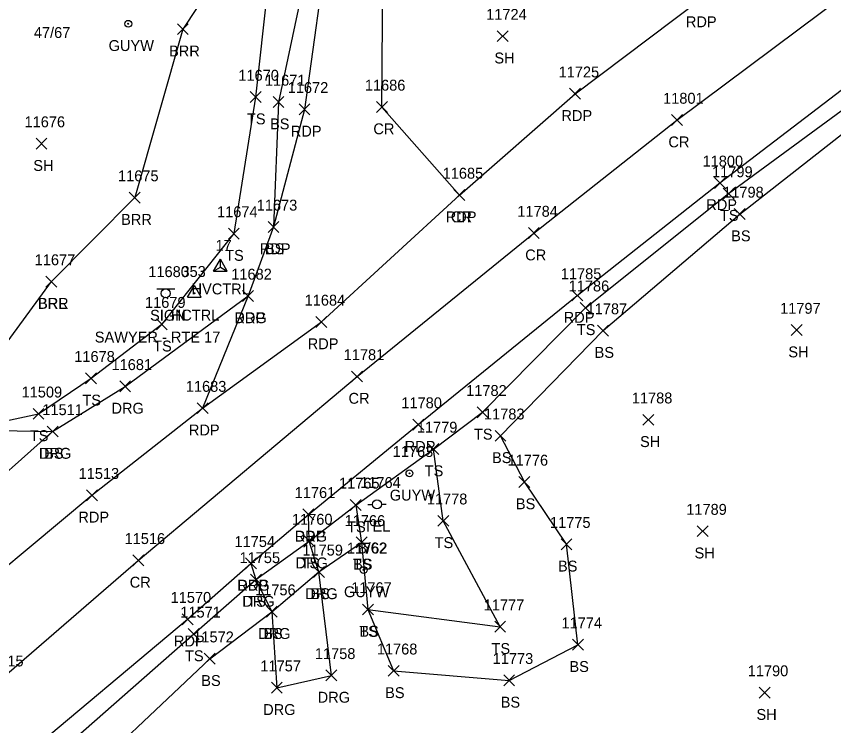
# Model space of a CAD drawing. Extents: x 1475671 to 1477951, y 592661 to 593821.
# Drawn here: x 1476967.1 to 1477117.1, y 593424.9 to 593555 of the extents above; entities that cross this region are included whole.
import ezdxf

# ---------------------------------------------------------------- set-up
doc = ezdxf.new("R2010")
doc.units = 0
for name, color, linetype in [('C_A', 7, 'Continuous'), ('C_I', 7, 'Continuous'), ('CPH', 7, 'Continuous'), ('CPSM', 7, 'Continuous'), ('L_A', 7, 'Continuous'), ('L_I', 7, 'Continuous'), ('L_TIC', 7, 'Continuous'), ('LABL', 7, 'Continuous'), ('LELB', 7, 'Continuous'), ('P_A', 7, 'Continuous'), ('P_I', 7, 'Continuous'), ('P_TIC', 7, 'Continuous'), ('PET', 7, 'Continuous'), ('PRC', 7, 'Continuous'), ('R_A', 7, 'Continuous'), ('R_I', 7, 'Continuous'), ('R_TIC', 7, 'Continuous'), ('RDG', 7, 'Continuous'), ('S_A', 7, 'Continuous'), ('S_C', 7, 'Continuous'), ('S_I', 7, 'Continuous'), ('SSGN', 7, 'Continuous'), ('U_A', 7, 'Continuous'), ('U_C', 7, 'Continuous'), ('U_I', 7, 'Continuous'), ('UP', 7, 'Continuous'), ('UPGW', 7, 'Continuous')]:
    doc.layers.add(name, color=color, linetype=linetype)

msp = doc.modelspace()

# ---------------------------------------------------------------- linework, layer by layer
at = {"layer": 'CPH'}
for p, q in [((1476998.52, 593503.53), (1476999.77, 593505.7)), ((1477001.02, 593503.53), (1476999.77, 593505.7)), ((1476999.78, 593504.25), (1476999.78, 593504.25)), ((1476998.52, 593503.53), (1477001.02, 593503.53))]:
    msp.add_line(p, q, dxfattribs=at)
msp.add_circle((1476999.78, 593504.25), 0.0833, dxfattribs=at)
at = {"layer": 'CPSM'}
for p, q in [((1477003.31, 593508.33), (1477004.56, 593510.49)), ((1477005.81, 593508.33), (1477004.56, 593510.49)), ((1477004.56, 593509.05), (1477004.56, 593510.49)), ((1477003.31, 593508.33), (1477004.56, 593509.05)), ((1477003.31, 593508.33), (1477005.81, 593508.33)), ((1477004.56, 593509.05), (1477004.56, 593509.05)), ((1477004.56, 593509.05), (1477005.81, 593508.33))]:
    msp.add_line(p, q, dxfattribs=at)
at = {"layer": 'L_TIC'}
for points in [[(1476996.65, 593551.69), (1476998.65, 593553.69)], [(1476998.65, 593551.69), (1476996.65, 593553.69)], [(1477055.34, 593550.41), (1477057.34, 593552.41)], [(1477057.34, 593550.41), (1477055.34, 593552.41)], [(1477010.01, 593539.24), (1477012.01, 593541.24)], [(1477012.01, 593539.24), (1477010.01, 593541.24)], [(1477014.22, 593538.33), (1477016.22, 593540.33)], [(1477016.22, 593538.33), (1477014.22, 593540.33)], [(1476970.73, 593530.7), (1476972.73, 593532.7)], [(1476972.73, 593530.7), (1476970.73, 593532.7)], [(1477096.81, 593521.54), (1477098.81, 593523.54)], [(1477098.81, 593521.54), (1477096.81, 593523.54)], [(1476987.84, 593520.8), (1476989.84, 593522.8)], [(1476989.84, 593520.8), (1476987.84, 593522.8)], [(1477098.84, 593517.79), (1477100.84, 593519.79)], [(1477100.84, 593517.79), (1477098.84, 593519.79)], [(1477013.29, 593515.42), (1477015.29, 593517.42)], [(1477015.29, 593515.42), (1477013.29, 593517.42)], [(1477006.01, 593514.21), (1477008.01, 593516.21)], [(1477008.01, 593514.21), (1477006.01, 593516.21)], [(1476972.55, 593505.4), (1476974.55, 593507.4)], [(1476974.55, 593505.4), (1476972.55, 593507.4)], [(1476972.55, 593505.4), (1476974.55, 593507.4)], [(1476974.55, 593505.4), (1476972.55, 593507.4)], [(1477070.54, 593500.59), (1477072.54, 593502.59)], [(1477072.54, 593500.59), (1477070.54, 593502.59)], [(1476992.8, 593497.58), (1476994.8, 593499.58)], [(1476994.8, 593497.58), (1476992.8, 593499.58)], [(1476992.8, 593497.58), (1476994.8, 593499.58)], [(1476994.8, 593497.58), (1476992.8, 593499.58)], [(1477073.78, 593496.41), (1477075.78, 593498.41)], [(1477075.78, 593496.41), (1477073.78, 593498.41)], [(1477109.28, 593496.5), (1477111.28, 593498.5)], [(1477111.28, 593496.5), (1477109.28, 593498.5)], [(1476979.82, 593487.66), (1476981.82, 593489.66)], [(1476981.82, 593487.66), (1476979.82, 593489.66)], [(1476970.18, 593481.14), (1476972.18, 593483.14)], [(1476972.18, 593481.14), (1476970.18, 593483.14)], [(1477051.67, 593481.42), (1477053.67, 593483.42)], [(1477053.67, 593481.42), (1477051.67, 593483.42)], [(1477082.08, 593480.05), (1477084.08, 593482.05)], [(1477084.08, 593480.05), (1477082.08, 593482.05)], [(1476972.77, 593477.9), (1476974.77, 593479.9)], [(1476974.77, 593477.9), (1476972.77, 593479.9)], [(1477054.95, 593477.11), (1477056.95, 593479.11)], [(1477056.95, 593477.11), (1477054.95, 593479.11)], [(1477054.95, 593477.11), (1477056.95, 593479.11)], [(1477056.95, 593477.11), (1477054.95, 593479.11)], [(1477042.63, 593474.69), (1477044.63, 593476.69)], [(1477044.63, 593474.69), (1477042.63, 593476.69)], [(1477042.63, 593474.69), (1477044.63, 593476.69)], [(1477044.63, 593474.69), (1477042.63, 593476.69)], [(1477059.33, 593468.64), (1477061.33, 593470.64)], [(1477061.33, 593468.64), (1477059.33, 593470.64)], [(1477028.39, 593464.42), (1477030.39, 593466.42)], [(1477030.39, 593464.42), (1477028.39, 593466.42)], [(1477028.39, 593464.42), (1477030.39, 593466.42)], [(1477030.39, 593464.42), (1477028.39, 593466.42)], [(1477044.45, 593461.52), (1477046.45, 593463.52)], [(1477046.45, 593461.52), (1477044.45, 593463.52)], [(1477092.07, 593459.62), (1477094.07, 593461.62)], [(1477094.07, 593459.62), (1477092.07, 593461.62)], [(1477019.84, 593457.8), (1477021.84, 593459.8)], [(1477021.84, 593457.8), (1477019.84, 593459.8)], [(1477029.46, 593457.56), (1477031.46, 593459.56)], [(1477031.46, 593457.56), (1477029.46, 593459.56)], [(1477029.46, 593457.56), (1477031.46, 593459.56)], [(1477031.46, 593457.56), (1477029.46, 593459.56)], [(1477067.06, 593457.22), (1477069.06, 593459.22)], [(1477069.06, 593457.22), (1477067.06, 593459.22)], [(1477021.63, 593452.15), (1477023.63, 593454.15)], [(1477023.63, 593452.15), (1477021.63, 593454.15)], [(1477010.08, 593450.76), (1477012.08, 593452.76)], [(1477012.08, 593450.76), (1477010.08, 593452.76)], [(1477012.99, 593444.85), (1477014.99, 593446.85)], [(1477014.99, 593444.85), (1477012.99, 593446.85)], [(1477030.62, 593445.25), (1477032.62, 593447.25)], [(1477032.62, 593445.25), (1477030.62, 593447.25)], [(1477030.62, 593445.25), (1477032.62, 593447.25)], [(1477032.62, 593445.25), (1477030.62, 593447.25)], [(1477054.89, 593442.09), (1477056.89, 593444.09)], [(1477056.89, 593442.09), (1477054.89, 593444.09)], [(1476998.65, 593440.77), (1477000.65, 593442.77)], [(1477000.65, 593440.77), (1476998.65, 593442.77)], [(1477069.16, 593438.79), (1477071.16, 593440.79)], [(1477071.16, 593438.79), (1477069.16, 593440.79)], [(1477001.6, 593436.22), (1477003.6, 593438.22)], [(1477003.6, 593436.22), (1477001.6, 593438.22)], [(1477035.34, 593434), (1477037.34, 593436)], [(1477037.34, 593434), (1477035.34, 593436)], [(1477056.55, 593432.26), (1477058.55, 593434.26)], [(1477058.55, 593432.26), (1477056.55, 593434.26)], [(1477103.43, 593430.01), (1477105.43, 593432.01)], [(1477105.43, 593430.01), (1477103.43, 593432.01)]]:
    msp.add_lwpolyline(points, dxfattribs=at)
at = {"layer": 'LABL'}
for points in [[(1476911.91, 593510.8), (1476912.49, 593516.79), (1476929.85, 593528.26), (1476933.94, 593533.82), (1476958.76, 593554.62), (1476973.11, 593571.96), (1476990.92, 593600.35), (1477003.39, 593627.65), (1477008.63, 593642.74), (1477022.23, 593640.46), (1477021.13, 593611.9), (1477015.31, 593579.47), (1476997.65, 593552.69), (1476988.84, 593521.8), (1476973.55, 593506.4)], [(1476911.91, 593510.8), (1476918.01, 593495.51), (1476939.54, 593493.76), (1476961.41, 593489.82), (1476973.55, 593506.4)]]:
    msp.add_lwpolyline(points, dxfattribs=at)
at = {"layer": 'LELB'}
for points in [[(1477055.95, 593478.11), (1477074.78, 593497.41), (1477099.84, 593518.79), (1477134.38, 593545.79), (1477166.94, 593568.76), (1477207.75, 593594.56), (1477237.01, 593614.27), (1477256.43, 593624.24), (1477293.96, 593641.04), (1477304.8, 593646.41), (1477345.23, 593662.26), (1477383.56, 593674.31), (1477424.33, 593683.35), (1477474.43, 593689.99), (1477503.05, 593695.22), (1477531.19, 593697.25), (1477568.45, 593701.91)], [(1476971.56, 593573.4), (1476985.93, 593604.48), (1476994.55, 593629.97), (1477003.49, 593645.65), (1477011.62, 593668.92), (1477016.36, 593671.4), (1477028.62, 593686.72), (1477037.33, 593699.08), (1477030.58, 593665.1), (1477026.73, 593650.69), (1477024.06, 593610.16), (1477021.85, 593570.52), (1477015.22, 593539.33), (1477014.29, 593516.42)], [(1476970.32, 593415.97), (1476999.65, 593441.77), (1477011.08, 593451.76), (1477020.84, 593458.8), (1477029.39, 593465.42), (1477043.63, 593475.69), (1477052.67, 593482.42), (1477071.54, 593501.59), (1477097.81, 593522.54), (1477132.73, 593548.15), (1477165.81, 593571.26), (1477206.03, 593598.34), (1477236.29, 593616.29), (1477255.56, 593625.95), (1477292.71, 593644.19), (1477303.48, 593648.85), (1477344.61, 593663.93), (1477382.86, 593676.29), (1477423.58, 593686.25), (1477474.01, 593693.84)], [(1477015.31, 593579.47), (1477011.01, 593540.24), (1477007.01, 593515.21), (1476993.8, 593498.58)], [(1476957.43, 593479.2), (1476971.18, 593482.14), (1476980.82, 593488.66), (1476993.8, 593498.58)], [(1476660.79, 593199.46), (1476674.63, 593214.33), (1476703.92, 593243.37), (1476720.54, 593255.98), (1476751.7, 593282.61), (1476781.77, 593307.79), (1476789.04, 593316.89), (1476807.89, 593333.24), (1476839.71, 593357.28), (1476859.97, 593374.46), (1476882.16, 593391.96), (1476882.87, 593395.08), (1476884.75, 593398.78), (1476886.94, 593401.06), (1476880.92, 593405.09), (1476872.21, 593402.61), (1476869.35, 593406.91), (1476883.46, 593416.6), (1476894.87, 593423.54), (1476922.16, 593439.01), (1476941.74, 593451.3), (1476958.3, 593465.19), (1476973.77, 593478.9)], [(1477031.62, 593446.25), (1477036.34, 593435), (1477057.55, 593433.26), (1477070.16, 593439.79), (1477068.06, 593458.22), (1477060.33, 593469.64), (1477055.95, 593478.11)], [(1477029.39, 593465.42), (1477030.46, 593458.56), (1477031.62, 593446.25), (1477055.89, 593443.09), (1477045.45, 593462.52), (1477043.63, 593475.69)], [(1476962.15, 593268.55), (1476966.09, 593293.73), (1476962.04, 593313.07), (1476957.94, 593342.76), (1476956.85, 593364.92), (1476946.71, 593381.5), (1476947.26, 593385.01), (1476945.57, 593387.27), (1476956.77, 593393.64), (1476963.43, 593396.59), (1476970.91, 593403.07), (1476974.88, 593411.06), (1477002.6, 593437.22), (1477013.99, 593445.85), (1477022.63, 593453.15), (1477030.46, 593458.56)]]:
    msp.add_lwpolyline(points, dxfattribs=at)
at = {"layer": 'P_TIC'}
for points in [[(1477068.64, 593539.85), (1477070.64, 593541.85)], [(1477070.64, 593539.85), (1477068.64, 593541.85)], [(1477018.98, 593536.99), (1477020.98, 593538.99)], [(1477020.98, 593536.99), (1477018.98, 593538.99)], [(1477033.19, 593537.42), (1477035.19, 593539.42)], [(1477035.19, 593537.42), (1477033.19, 593539.42)], [(1477087.32, 593535.02), (1477089.32, 593537.02)], [(1477089.32, 593535.02), (1477087.32, 593537.02)], [(1477095.22, 593523.5), (1477097.22, 593525.5)], [(1477097.22, 593523.5), (1477095.22, 593525.5)], [(1477047.41, 593521.27), (1477049.41, 593523.27)], [(1477049.41, 593521.27), (1477047.41, 593523.27)], [(1477047.41, 593521.27), (1477049.41, 593523.27)], [(1477049.41, 593521.27), (1477047.41, 593523.27)], [(1477013.29, 593515.42), (1477015.29, 593517.42)], [(1477015.29, 593515.42), (1477013.29, 593517.42)], [(1477061.06, 593514.29), (1477063.06, 593516.29)], [(1477063.06, 593514.29), (1477061.06, 593516.29)], [(1477008.62, 593502.76), (1477010.62, 593504.76)], [(1477010.62, 593502.76), (1477008.62, 593504.76)], [(1477069.05, 593502.84), (1477071.05, 593504.84)], [(1477071.05, 593502.84), (1477069.05, 593504.84)], [(1477022.09, 593497.99), (1477024.09, 593499.99)], [(1477024.09, 593497.99), (1477022.09, 593499.99)], [(1477028.64, 593487.99), (1477030.64, 593489.99)], [(1477030.64, 593487.99), (1477028.64, 593489.99)], [(1477000.29, 593482.18), (1477002.29, 593484.18)], [(1477002.29, 593482.18), (1477000.29, 593484.18)], [(1477000.29, 593482.18), (1477002.29, 593484.18)], [(1477002.29, 593482.18), (1477000.29, 593484.18)], [(1477039.87, 593479.17), (1477041.87, 593481.17)], [(1477041.87, 593479.17), (1477039.87, 593481.17)], [(1476979.99, 593466.2), (1476981.99, 593468.2)], [(1476981.99, 593466.2), (1476979.99, 593468.2)], [(1477019.69, 593462.7), (1477021.69, 593464.7)], [(1477021.69, 593462.7), (1477019.69, 593464.7)], [(1476988.48, 593454.26), (1476990.48, 593456.26)], [(1476990.48, 593454.26), (1476988.48, 593456.26)], [(1477009.16, 593453.71), (1477011.16, 593455.71)], [(1477011.16, 593453.71), (1477009.16, 593455.71)], [(1476997.53, 593443.47), (1476999.53, 593445.47)], [(1476999.53, 593443.47), (1476997.53, 593445.47)]]:
    msp.add_lwpolyline(points, dxfattribs=at)
at = {"layer": 'PET'}
for points in [[(1476922.98, 593419.08), (1476952.36, 593443.37), (1476980.99, 593467.2), (1477001.29, 593483.18), (1477023.09, 593498.99), (1477048.41, 593522.27), (1477069.64, 593540.85), (1477092.48, 593558.05), (1477107.82, 593567.96), (1477124.14, 593580.14), (1477159.25, 593604.27), (1477192.28, 593625.33), (1477229.26, 593646.84), (1477278.16, 593671.86), (1477332.19, 593694.33), (1477375.16, 593706.96), (1477415.75, 593716.85), (1477468.99, 593725.32)], [(1476967.73, 593418.7), (1476998.53, 593444.47), (1477010.16, 593454.71), (1477020.69, 593463.7), (1477040.87, 593480.17), (1477070.05, 593503.84), (1477096.22, 593524.5), (1477130.86, 593550.96), (1477164.87, 593573.97), (1477205.52, 593600.91), (1477235.56, 593618.03), (1477291.48, 593646.91), (1477343.59, 593667.49), (1477381.85, 593678.97), (1477423.34, 593689.19), (1477473.94, 593697.4)], [(1477040.93, 593697.02), (1477035.4, 593666.2), (1477032.31, 593649.16), (1477028.23, 593610.02), (1477024.47, 593570.17), (1477019.98, 593537.99), (1477014.29, 593516.42), (1477009.62, 593503.76), (1477001.29, 593483.18)]]:
    msp.add_lwpolyline(points, dxfattribs=at)
at = {"layer": 'PRC'}
for points in [[(1476934.06, 593407.68), (1476963.46, 593432.81), (1476989.48, 593455.26), (1477029.64, 593488.99), (1477062.06, 593515.29), (1477088.32, 593536.02), (1477123.8, 593562.56), (1477162.82, 593589.95), (1477199.33, 593613.78), (1477232.88, 593633.31), (1477283.55, 593659.16), (1477336.93, 593680.98), (1477378.09, 593693.68), (1477418.39, 593702.94), (1477470.82, 593711.77)], [(1477048.41, 593522.27), (1477034.19, 593538.42), (1477034.44, 593570.14), (1477037.89, 593611.13), (1477043.98, 593653.2), (1477051.59, 593695.26)]]:
    msp.add_lwpolyline(points, dxfattribs=at)
at = {"layer": 'R_TIC'}
for points in [[(1477008.62, 593502.76), (1477010.62, 593504.76)], [(1477010.62, 593502.76), (1477008.62, 593504.76)], [(1476986.07, 593486.17), (1476988.07, 593488.17)], [(1476988.07, 593486.17), (1476986.07, 593488.17)], [(1476972.77, 593477.9), (1476974.77, 593479.9)], [(1476974.77, 593477.9), (1476972.77, 593479.9)], [(1477019.69, 593462.7), (1477021.69, 593464.7)], [(1477021.69, 593462.7), (1477019.69, 593464.7)], [(1477019.84, 593457.8), (1477021.84, 593459.8)], [(1477021.84, 593457.8), (1477019.84, 593459.8)], [(1477009.16, 593453.71), (1477011.16, 593455.71)], [(1477011.16, 593453.71), (1477009.16, 593455.71)], [(1477021.63, 593452.15), (1477023.63, 593454.15)], [(1477023.63, 593452.15), (1477021.63, 593454.15)], [(1477010.08, 593450.76), (1477012.08, 593452.76)], [(1477012.08, 593450.76), (1477010.08, 593452.76)], [(1477012.99, 593444.85), (1477014.99, 593446.85)], [(1477014.99, 593444.85), (1477012.99, 593446.85)], [(1477023.91, 593433.16), (1477025.91, 593435.16)], [(1477025.91, 593433.16), (1477023.91, 593435.16)], [(1477013.91, 593430.9), (1477015.91, 593432.9)], [(1477015.91, 593430.9), (1477013.91, 593432.9)]]:
    msp.add_lwpolyline(points, dxfattribs=at)
at = {"layer": 'RDG'}
for points in [[(1476833.75, 593461.63), (1476850.34, 593445.61), (1476868.94, 593435.34), (1476881.96, 593436.68), (1476878.58, 593445.34), (1476869.69, 593462.49), (1476881.62, 593465.91), (1476887.63, 593455.44), (1476895.18, 593445.46), (1476901.06, 593440.89), (1476907.76, 593443.2), (1476918.93, 593450.79), (1476925.87, 593461.59), (1476922.94, 593472.26), (1476913.39, 593479.07), (1476902.11, 593485.18), (1476906.06, 593495.8), (1476919.07, 593489.89), (1476940.37, 593483.2), (1476957.43, 593479.2), (1476973.77, 593478.9), (1476987.07, 593487.17), (1477009.62, 593503.76)], [(1477010.16, 593454.71), (1477011.08, 593451.76), (1477013.99, 593445.85), (1477014.91, 593431.9), (1477024.91, 593434.16), (1477022.63, 593453.15), (1477020.84, 593458.8), (1477020.69, 593463.7)]]:
    msp.add_lwpolyline(points, dxfattribs=at)
at = {"layer": 'SSGN'}
for p, q in [((1476992.86, 593505.07), (1476996.2, 593505.07)), ((1476994.51, 593504.24), (1476994.51, 593504.24))]:
    msp.add_line(p, q, dxfattribs=at)
msp.add_circle((1476994.51, 593504.24), 0.833, dxfattribs=at)
at = {"layer": 'UP'}
for p, q in [((1477031.62, 593465.53), (1477032.45, 593465.53)), ((1477033.28, 593465.54), (1477033.28, 593465.54)), ((1477034.95, 593465.54), (1477034.12, 593465.54)), ((1477034.12, 593465.54), (1477034.12, 593465.54)), ((1477034.95, 593465.54), (1477034.95, 593465.54))]:
    msp.add_line(p, q, dxfattribs=at)
msp.add_circle((1477033.28, 593465.54), 0.833, dxfattribs=at)
at = {"layer": 'UPGW'}
for centre, radius in [((1476987.65, 593553.69), 0.625), ((1476987.65, 593553.69), 0.0833), ((1477039.24, 593471.23), 0.625), ((1477039.24, 593471.23), 0.0833), ((1477030.83, 593453.51), 0.625), ((1477030.83, 593453.51), 0.0833)]:
    msp.add_circle(centre, radius, dxfattribs=at)

# ---------------------------------------------------------------- texts
at = {"layer": 'C_A'}
for s, p in [('HVCTRL', (1476999.25, 593504.05)), ('HCTRL', (1476995.44, 593499.25))]:
    msp.add_text(s, height=2, dxfattribs=at).set_placement(p)
at = {"layer": 'C_I'}
for s, p in [('17', (1477003.66, 593512.05)), ('353', (1476997.41, 593507.25))]:
    msp.add_text(s, height=2, dxfattribs=at).set_placement(p)
at = {"layer": 'L_A'}
for s, p in [('BRR', (1476995.13, 593547.69)), ('SH', (1477054.83, 593546.41)), ('TS', (1477009.42, 593535.24)), ('BS', (1477013.66, 593534.33)), ('SH', (1476970.22, 593526.7)), ('BRR', (1476986.33, 593516.8)), ('TS', (1477096.22, 593517.54)), ('BS', (1477098.28, 593513.79)), ('BS', (1477012.73, 593511.42)), ('TS', (1477005.42, 593510.21)), ('BRR', (1476971.04, 593501.4)), ('BRL', (1476971.1, 593501.4)), ('TS', (1477069.95, 593496.59)), ('TS', (1476992.21, 593493.58)), ('TS', (1476992.21, 593493.58)), ('BS', (1477073.22, 593492.41)), ('SH', (1477108.77, 593492.5)), ('TS', (1476979.23, 593483.66)), ('TS', (1476969.59, 593477.14)), ('TS', (1477051.08, 593477.42)), ('SH', (1477081.56, 593476.05)), ('BS', (1476972.21, 593473.9)), ('BS', (1477054.39, 593473.11)), ('BS', (1477054.39, 593473.11)), ('TS', (1477042.04, 593470.69)), ('TS', (1477042.04, 593470.69)), ('BS', (1477058.77, 593464.64)), ('TS', (1477027.8, 593460.42)), ('TS', (1477027.8, 593460.42)), ('TS', (1477043.86, 593457.52)), ('SH', (1477091.56, 593455.62)), ('TS', (1477019.25, 593453.8)), ('TS', (1477028.87, 593453.56)), ('BS', (1477028.9, 593453.56)), ('BS', (1477066.5, 593453.22)), ('BS', (1477021.07, 593448.15)), ('TS', (1477009.49, 593446.76)), ('BS', (1477012.43, 593440.85)), ('TS', (1477030.03, 593441.25)), ('BS', (1477030.06, 593441.25)), ('TS', (1477054.3, 593438.09)), ('TS', (1476998.06, 593436.77)), ('BS', (1477068.6, 593434.79)), ('BS', (1477001.04, 593432.22)), ('BS', (1477034.78, 593430)), ('BS', (1477055.99, 593428.26)), ('SH', (1477102.92, 593426.01))]:
    msp.add_text(s, height=2, dxfattribs=at).set_placement(p)
at = {"layer": 'L_I'}
for s, p in [('11724', (1477053.32, 593554.41)), ('11670', (1477007.85, 593543.24)), ('11671', (1477012.72, 593542.33)), ('11676', (1476968.61, 593534.7)), ('11799', (1477094.78, 593525.54)), ('11675', (1476985.77, 593524.8)), ('11798', (1477096.81, 593521.79)), ('11674', (1477003.94, 593518.21)), ('11673', (1477011.22, 593519.42)), ('11677', (1476970.48, 593509.4)), ('11677', (1476970.48, 593509.4)), ('11786', (1477068.46, 593504.59)), ('11679', (1476990.72, 593501.58)), ('11679', (1476990.72, 593501.58)), ('11787', (1477071.76, 593500.41)), ('11797', (1477107.26, 593500.5)), ('11678', (1476977.74, 593491.66)), ('11509', (1476968.07, 593485.14)), ('11782', (1477049.65, 593485.42)), ('11788', (1477080.05, 593484.05)), ('11511', (1476971.88, 593481.9)), ('11783', (1477052.92, 593481.11)), ('11783', (1477052.92, 593481.11)), ('11779', (1477040.6, 593478.69)), ('11779', (1477040.6, 593478.69)), ('11776', (1477057.25, 593472.64)), ('11765', (1477026.32, 593468.42)), ('11765', (1477026.32, 593468.42)), ('11778', (1477042.43, 593465.52)), ('11789', (1477090.04, 593463.62)), ('11760', (1477017.69, 593461.8)), ('11766', (1477027.34, 593461.56)), ('11766', (1477027.34, 593461.56)), ('11775', (1477065.04, 593461.22)), ('11759', (1477019.6, 593456.15)), ('11755', (1477008.06, 593454.76)), ('11767', (1477028.55, 593449.25)), ('11767', (1477028.55, 593449.25)), ('11756', (1477010.92, 593448.85)), ('11777', (1477052.87, 593446.09)), ('11571', (1476997.2, 593444.77)), ('11774', (1477067.14, 593442.79)), ('11572', (1476999.58, 593440.22)), ('11768', (1477033.26, 593438)), ('11773', (1477054.52, 593436.26)), ('11790', (1477101.32, 593434.01))]:
    msp.add_text(s, height=2, dxfattribs=at).set_placement(p)
at = {"layer": 'P_A'}
for s, p in [('RDP', (1477089.97, 593553.05)), ('RDP', (1477089.97, 593553.05)), ('RDP', (1477067.13, 593535.85)), ('CR', (1477032.62, 593533.42)), ('RDP', (1477017.47, 593532.99)), ('CR', (1477086.76, 593531.02)), ('RDP', (1477093.71, 593519.5)), ('RDP', (1477045.9, 593517.27)), ('CR', (1477046.85, 593517.27)), ('RDP', (1477011.78, 593511.42)), ('CR', (1477060.49, 593510.29)), ('RDP', (1477007.11, 593498.76)), ('RDP', (1477067.54, 593498.84)), ('RDP', (1477020.57, 593493.99)), ('CR', (1477028.07, 593483.99)), ('RDP', (1476998.77, 593478.18)), ('RDP', (1476998.77, 593478.18)), ('RDP', (1477038.36, 593475.17)), ('RDP', (1476978.48, 593462.2)), ('RDP', (1477018.18, 593458.7)), ('CR', (1476987.91, 593450.26)), ('RDP', (1477007.65, 593449.71)), ('RDP', (1476996.02, 593439.47))]:
    msp.add_text(s, height=2, dxfattribs=at).set_placement(p)
at = {"layer": 'P_I'}
for s, p in [('11725', (1477066.62, 593543.85)), ('11672', (1477016.91, 593540.99)), ('11686', (1477031.06, 593541.42)), ('11801', (1477085.79, 593539.02)), ('11800', (1477093.03, 593527.5)), ('11685', (1477045.34, 593525.27)), ('11685', (1477045.34, 593525.27)), ('11673', (1477011.22, 593519.42)), ('11784', (1477059.04, 593518.29)), ('11682', (1477006.55, 593506.76)), ('11785', (1477067.02, 593506.84)), ('11684', (1477020.01, 593501.99)), ('11781', (1477027.18, 593491.99)), ('11683', (1476998.21, 593486.18)), ('11683', (1476998.21, 593486.18)), ('11780', (1477037.76, 593483.17)), ('11513', (1476978.54, 593470.2)), ('11761', (1477018.19, 593466.7)), ('11516', (1476986.97, 593458.26)), ('11754', (1477007.14, 593457.71)), ('11570', (1476995.42, 593447.47)), ('11515', (1476961, 593435.81))]:
    msp.add_text(s, height=2, dxfattribs=at).set_placement(p)
at = {"layer": 'R_A'}
for p in [(1477007.11, 593498.76), (1476984.56, 593482.17), (1476971.26, 593473.9), (1477018.18, 593458.7), (1477018.33, 593453.8), (1477007.65, 593449.71), (1477020.12, 593448.15), (1477008.57, 593446.76), (1477011.48, 593440.85), (1477022.4, 593429.16), (1477012.4, 593426.9)]:
    msp.add_text('DRG', height=2, dxfattribs=at).set_placement(p)
at = {"layer": 'R_I'}
for s, p in [('11682', (1477006.55, 593506.76)), ('11681', (1476984.57, 593490.17)), ('11511', (1476971.88, 593481.9)), ('11761', (1477018.19, 593466.7)), ('11760', (1477017.69, 593461.8)), ('11754', (1477007.14, 593457.71)), ('11759', (1477019.6, 593456.15)), ('11755', (1477008.06, 593454.76)), ('11756', (1477010.92, 593448.85)), ('11758', (1477021.89, 593437.16)), ('11757', (1477011.89, 593434.9))]:
    msp.add_text(s, height=2, dxfattribs=at).set_placement(p)
at = {"layer": 'S_A'}
msp.add_text('SIGN', height=2, dxfattribs=at).set_placement((1476991.65, 593499.22))
at = {"layer": 'S_C'}
msp.add_text('SAWYER - RTE 17', height=2, dxfattribs=at).set_placement((1476981.5, 593495.22))
at = {"layer": 'S_I'}
msp.add_text('11680', height=2, dxfattribs=at).set_placement((1476991.33, 593507.22))
at = {"layer": 'U_A'}
for s, p in [('GUYW', (1476984.04, 593548.69)), ('GUYW', (1477035.63, 593466.23)), ('TEL', (1477030.84, 593460.54)), ('GUYW', (1477027.23, 593448.51))]:
    msp.add_text(s, height=2, dxfattribs=at).set_placement(p)
at = {"layer": 'U_C'}
for s, p in [('47/67', (1476970.32, 593551.08)), ('8/62', (1477029.9, 593456.54))]:
    msp.add_text(s, height=2, dxfattribs=at).set_placement(p)
at = {"layer": 'U_I'}
for s, p in [('11763', (1477036.17, 593474.23)), ('11764', (1477030.21, 593468.54)), ('11762', (1477027.76, 593456.51))]:
    msp.add_text(s, height=2, dxfattribs=at).set_placement(p)

doc.saveas('drawing.dxf')
